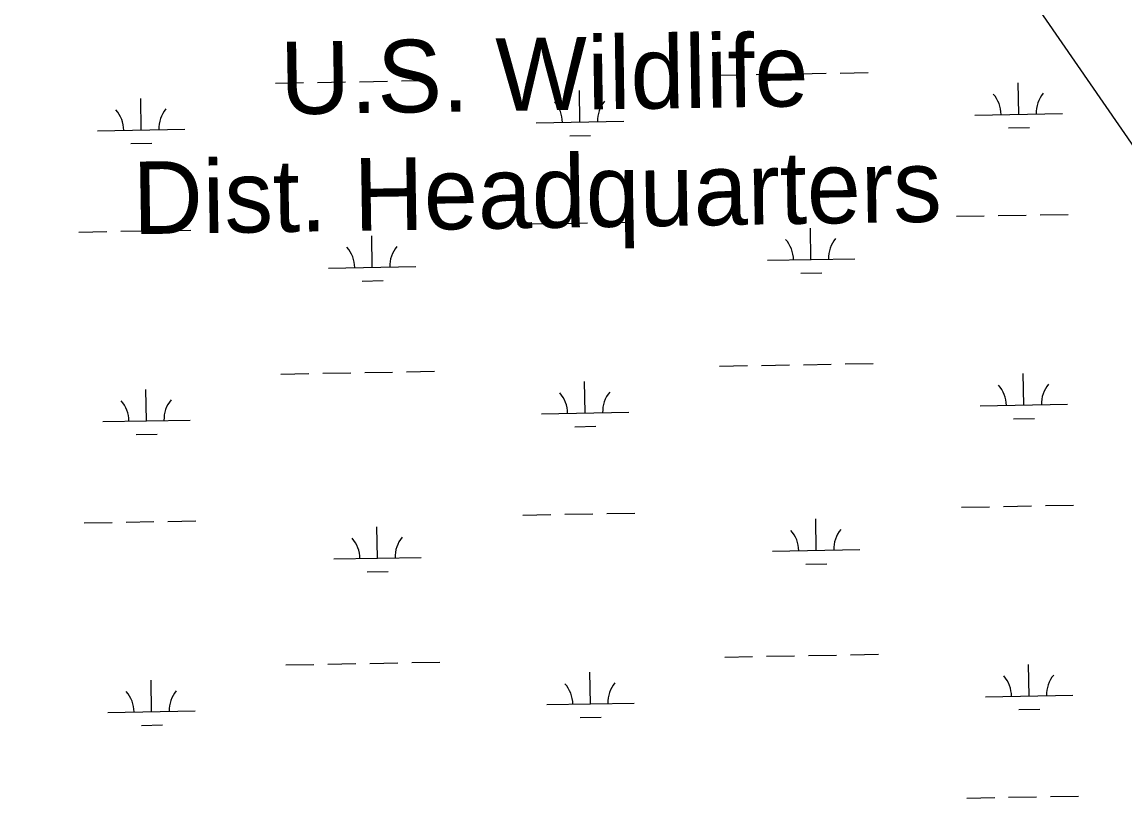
# Model space of a CAD drawing. Extents: x 3914892 to 3953151, y 242587 to 268572.
# Drawn here: x 3937258 to 3938519, y 263942 to 264831 of the extents above; entities that cross this region are included whole.
import ezdxf

# ---------------------------------------------------------------- set-up
doc = ezdxf.new("R2010")
doc.units = 0
for name, color, linetype in [('V-BLDG-IDEN', 7, 'Continuous'), ('V-UTIL-LINE', 7, 'Continuous'), ('V-WETL-SWMP', 7, 'Continuous')]:
    doc.layers.add(name, color=color, linetype=linetype)

msp = doc.modelspace()

# ---------------------------------------------------------------- linework, layer by layer
at = {"layer": 'V-UTIL-LINE'}
msp.add_lwpolyline([(3937257.7, 266529.8), (3940896.3, 261259), (3942305.5, 257189.6), (3945242.9, 251786.9), (3947661.4, 248530.4)], dxfattribs=at)
at = {"layer": 'V-WETL-SWMP'}
for p, q in [((3937643.7, 264762.5), (3937675.7, 264763.1)), ((3937691.7, 264763.4), (3937723.7, 264764)), ((3938049.5, 264769.8), (3938081.5, 264770.4)), ((3938097.5, 264770.7), (3938129.5, 264771.2)), ((3938145.5, 264771.5), (3938177.5, 264772.1)), ((3938193.5, 264772.4), (3938225.5, 264773)), ((3937547.7, 264760.8), (3937579.7, 264761.4)), ((3937595.7, 264761.7), (3937627.7, 264762.3)), ((3937895.9, 264716.3), (3937895.2, 264752.3)), ((3938397.7, 264725.3), (3938397, 264761.3)), ((3937394, 264707.3), (3937393.4, 264743.3)), ((3938347.7, 264724.4), (3938447.7, 264726.2)), ((3937845.9, 264715.4), (3937945.9, 264717.2)), ((3937344, 264706.4), (3937444, 264708.2)), ((3937884.1, 264700.7), (3937908.1, 264701.1)), ((3938386, 264709.6), (3938410, 264710.1)), ((3937382.3, 264691.7), (3937406.3, 264692.1)), ((3937824.5, 264599.6), (3937856.5, 264600.2)), ((3937872.5, 264600.4), (3937904.5, 264601)), ((3937920.5, 264601.3), (3937952.5, 264601.9)), ((3938326.4, 264608.6), (3938358.3, 264609.1)), ((3938374.3, 264609.4), (3938406.3, 264610)), ((3938422.3, 264610.3), (3938454.3, 264610.8)), ((3937322.7, 264590.6), (3937354.7, 264591.2)), ((3937370.7, 264591.5), (3937402.7, 264592)), ((3937418.7, 264592.3), (3937450.7, 264592.9)), ((3937658.3, 264550.2), (3937657.7, 264586.2)), ((3938160.1, 264559.1), (3938159.5, 264595.1)), ((3937608.3, 264549.3), (3937708.3, 264551.1)), ((3938110.2, 264558.3), (3938210.1, 264560)), ((3938148.4, 264543.5), (3938172.4, 264543.9)), ((3937646.6, 264534.5), (3937670.6, 264535)), ((3938055.5, 264437.2), (3938087.5, 264437.8)), ((3938103.5, 264438), (3938135.5, 264438.6)), ((3938151.5, 264438.9), (3938183.4, 264439.5)), ((3938199.4, 264439.8), (3938231.4, 264440.3)), ((3937553.6, 264428.2), (3937585.6, 264428.8)), ((3937601.6, 264429.1), (3937633.6, 264429.6)), ((3937649.6, 264429.9), (3937681.6, 264430.5)), ((3937697.6, 264430.8), (3937729.6, 264431.4)), ((3938403.6, 264392.7), (3938403, 264428.7)), ((3937400, 264374.7), (3937399.3, 264410.7)), ((3937901.8, 264383.7), (3937901.2, 264419.7)), ((3937851.8, 264382.8), (3937951.8, 264384.6)), ((3938353.6, 264391.8), (3938453.6, 264393.6)), ((3937350, 264373.8), (3937450, 264375.6)), ((3938391.9, 264377), (3938415.9, 264377.4)), ((3937388.3, 264359.1), (3937412.3, 264359.5)), ((3937890.1, 264368), (3937914.1, 264368.5)), ((3938332.3, 264275.9), (3938364.3, 264276.5)), ((3938380.3, 264276.8), (3938412.3, 264277.4)), ((3938428.3, 264277.7), (3938460.3, 264278.2)), ((3937328.7, 264258), (3937360.6, 264258.6)), ((3937376.6, 264258.8), (3937408.6, 264259.4)), ((3937424.6, 264259.7), (3937456.6, 264260.3)), ((3937830.5, 264267), (3937862.5, 264267.5)), ((3937878.5, 264267.8), (3937910.5, 264268.4)), ((3937926.5, 264268.7), (3937958.5, 264269.2)), ((3938166.1, 264226.5), (3938165.5, 264262.5)), ((3937664.3, 264217.5), (3937663.6, 264253.5)), ((3938116.1, 264225.6), (3938216.1, 264227.4)), ((3937614.3, 264216.7), (3937714.3, 264218.4)), ((3938154.4, 264210.9), (3938178.4, 264211.3)), ((3937652.5, 264201.9), (3937676.5, 264202.3)), ((3938157.4, 264106.3), (3938189.4, 264106.9)), ((3938205.4, 264107.1), (3938237.4, 264107.7)), ((3937559.6, 264095.6), (3937591.6, 264096.2)), ((3937607.6, 264096.4), (3937639.6, 264097)), ((3937655.6, 264097.3), (3937687.6, 264097.9)), ((3937703.6, 264098.2), (3937735.6, 264098.7)), ((3938061.4, 264104.6), (3938093.4, 264105.1)), ((3938109.4, 264105.4), (3938141.4, 264106)), ((3938409.6, 264060), (3938408.9, 264096)), ((3937907.8, 264051.1), (3937907.1, 264087.1)), ((3937405.9, 264042.1), (3937405.3, 264078.1)), ((3938359.6, 264059.1), (3938459.6, 264060.9)), ((3937857.8, 264050.2), (3937957.8, 264052)), ((3938397.9, 264044.4), (3938421.9, 264044.8)), ((3937355.9, 264041.2), (3937455.9, 264043)), ((3937896, 264035.4), (3937920, 264035.8)), ((3937394.2, 264026.4), (3937418.2, 264026.9)), ((3938338.3, 263943.3), (3938370.3, 263943.9)), ((3938386.2, 263944.2), (3938418.2, 263944.7)), ((3938434.2, 263945), (3938466.2, 263945.6))]:
    msp.add_line(p, q, dxfattribs=at)
for centre, start, end in [((3937840.6, 264715.8), 0.2532, 41.7968), ((3937951.1, 264717.8), 140.2532, 181.7968), ((3938342.4, 264724.8), 0.2532, 41.7968), ((3938452.9, 264726.7), 140.2532, 181.7968), ((3937338.8, 264706.8), 0.2532, 41.7968), ((3937449.3, 264708.8), 140.2532, 181.7968), ((3937713.5, 264551.6), 140.2532, 181.7968), ((3938104.9, 264558.6), 0.2532, 41.7968), ((3938215.4, 264560.6), 140.2532, 181.7968), ((3937603.1, 264549.7), 0.2532, 41.7968), ((3938348.4, 264392.1), 0.2532, 41.7968), ((3938458.9, 264394.1), 140.2532, 181.7968), ((3937344.7, 264374.2), 0.2532, 41.7968), ((3937455.2, 264376.2), 140.2532, 181.7968), ((3937846.6, 264383.2), 0.2532, 41.7968), ((3937957, 264385.1), 140.2532, 181.7968), ((3938110.9, 264226), 0.2532, 41.7968), ((3938221.3, 264228), 140.2532, 181.7968), ((3937609, 264217), 0.2532, 41.7968), ((3937719.5, 264219), 140.2532, 181.7968), ((3938354.3, 264059.5), 0.2532, 41.7968), ((3938464.8, 264061.5), 140.2532, 181.7968), ((3937852.5, 264050.5), 0.2532, 41.7968), ((3937963, 264052.5), 140.2532, 181.7968), ((3937350.7, 264041.6), 0.2532, 41.7968), ((3937461.2, 264043.5), 140.2532, 181.7968)]:
    msp.add_arc(centre, 35.2, start, end, dxfattribs=at)

# ---------------------------------------------------------------- texts
at = {"layer": 'V-BLDG-IDEN'}
for s, p in [('U.S. Wildlife', (3937553.5, 264725.1)), ('Dist. Headquarters', (3937384.9, 264588))]:
    msp.add_text(s, height=83, rotation=0.8953, dxfattribs=at).set_placement(p)

doc.saveas('drawing.dxf')
